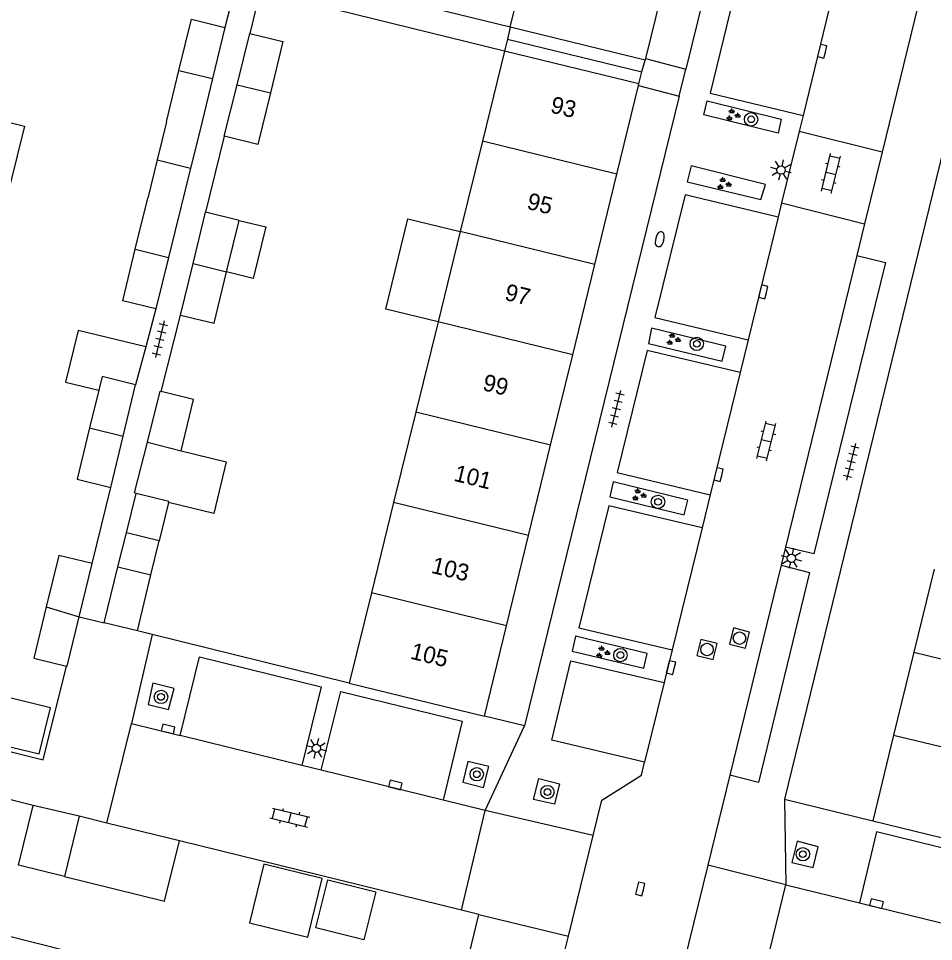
# Model space of a CAD drawing. Extents: x 128000 to 131008, y 398996 to 402500.
# Drawn here: x 128054.3 to 128108.9, y 399386.2 to 399441.3 of the extents above; entities that cross this region are included whole.
import ezdxf

# ---------------------------------------------------------------- set-up
doc = ezdxf.new("R2010")
doc.units = 0
for name, color, linetype in [('gg-afsc-erfafscheiding', 7, 'Continuous'), ('gg-afsc-muur', 7, 'Continuous'), ('gg-anno-huisnummerreeks BGT', 7, 'Continuous'), ('gg-bbg-bijgebouw', 7, 'Continuous'), ('gg-bbg-gedigitaliseerde bijgebouw', 7, 'Continuous'), ('gg-bbg-hoofdgebouw', 7, 'Continuous'), ('gg-bbg-luifel en loopbrug', 7, 'Continuous'), ('gg-bbg-onder overbouw', 7, 'Continuous'), ('gg-bbg-pand overbouw', 7, 'Continuous'), ('gg-bbg-tussenscheiding', 7, 'Continuous'), ('gg-bbg-tussenscheiding niveau 01', 7, 'Continuous'), ('gg-knt-verharding', 7, 'Continuous'), ('gg-knt-verharding nz', 7, 'Continuous'), ('gt-grn-weggrens', 7, 'Continuous'), ('gt-symb-boom', 7, 'Continuous'), ('gt-symb-brandkraan', 7, 'Continuous'), ('gt-symb-groenvak', 7, 'Continuous'), ('gt-symb-klinker verharding', 7, 'Continuous'), ('gt-symb-kolk', 7, 'Continuous'), ('gt-symb-lichtmast', 7, 'Continuous'), ('gt-symb-rioolschacht', 7, 'Continuous'), ('gt-symb-tegel verharding', 7, 'Continuous')]:
    doc.layers.add(name, color=color, linetype=linetype)

# ---------------------------------------------------------------- blocks, each defined once
blk = doc.blocks.new('gt0-KL1')
at = {"layer": 'gt-symb-klinker verharding'}
for p, q in [((-1.15, 0.3), (1.15, 0.3)), ((-1, -0.3), (-1, 0.3)), ((-0.5, 0.3), (-0.5, 0.45)), ((0, -0.3), (0, 0.3)), ((0.5, 0.3), (0.5, 0.45)), ((1, -0.3), (1, 0.3)), ((-1.15, -0.3), (1.15, -0.3)), ((-0.5, -0.45), (-0.5, -0.3)), ((0.5, -0.45), (0.5, -0.3))]:
    blk.add_line(p, q, dxfattribs=at)
blk = doc.blocks.new('gt0-KOLK')
at = {"layer": 'gt-symb-kolk'}
blk.add_lwpolyline([(0, 0), (0.375, 0), (0.375, 0.4), (-0.375, 0.4), (-0.375, 0), (0, 0)], dxfattribs=at)
blk = doc.blocks.new('gt0-TEG1')
at = {"layer": 'gt-symb-tegel verharding'}
for p, q in [((-1.125, 0), (1.125, 0)), ((-0.9, -0.25), (-0.9, 0.25)), ((-0.45, -0.25), (-0.45, 0.25)), ((0, -0.25), (0, 0.25)), ((0.45, -0.25), (0.45, 0.25)), ((0.9, -0.25), (0.9, 0.25))]:
    blk.add_line(p, q, dxfattribs=at)
blk = doc.blocks.new('gt0-LMAST')
at = {"layer": 'gt-symb-lichtmast'}
for p, q in [((-0.005, 0.246), (-0.005, 0.621)), ((-0.182, 0.173), (-0.447, 0.438)), ((0.172, 0.173), (0.437, 0.438)), ((-0.255, -0.004), (-0.63, -0.004)), ((-0.182, -0.181), (-0.447, -0.446)), ((-0.005, -0.254), (-0.005, -0.629)), ((0.437, -0.446), (0.172, -0.181)), ((0.245, -0.004), (0.62, -0.004))]:
    blk.add_line(p, q, dxfattribs=at)
blk.add_circle((-0.005, -0.004), 0.25, dxfattribs=at)
blk = doc.blocks.new('gt0-BOOM')
at = {"layer": 'gt-symb-boom'}
for radius in [0.4, 0.2]:
    blk.add_circle((0, 0), radius, dxfattribs=at)
blk = doc.blocks.new('gt0-GRVAK')
at = {"layer": 'gt-symb-groenvak'}
for p, q in [((-0.11, 0.189), (-0.228, 0.24)), ((-0.182, 0.153), (0.088, 0.153)), ((-0.091, 0.211), (-0.156, 0.322)), ((-0.047, 0.214), (-0.047, 0.393)), ((-0.004, 0.211), (0.061, 0.322)), ((0.015, 0.189), (0.133, 0.24)), ((0.262, -0.052), (0.197, 0.059)), ((0.305, -0.049), (0.305, 0.13)), ((0.349, -0.052), (0.414, 0.059)), ((-0.245, -0.228), (-0.363, -0.177)), ((-0.318, -0.264), (-0.047, -0.264)), ((-0.226, -0.206), (-0.291, -0.095)), ((-0.183, -0.203), (-0.183, -0.024)), ((-0.139, -0.206), (-0.074, -0.095)), ((-0.12, -0.228), (-0.002, -0.177)), ((0.243, -0.074), (0.125, -0.023)), ((0.17, -0.11), (0.441, -0.11)), ((0.368, -0.074), (0.486, -0.023))]:
    blk.add_line(p, q, dxfattribs=at)
blk = doc.blocks.new('gt0-BR')
at = {"layer": 'gt-symb-brandkraan'}
for centre, radius, start, end in [((-0.244, 0), 0.206, 107.5669, 252.4331), ((0.599, -2.664), 3, 106.892, 107.5669), ((0, -0.691), 0.938, 73.108, 106.892), ((-0.599, -2.664), 3, 72.4331, 73.108), ((0.244, 0), 0.206, 287.567, 72.4331), ((0.599, 2.664), 3, 252.4331, 253.108), ((0, 0.691), 0.938, 253.108, 286.8921), ((-0.599, 2.664), 3, 286.8921, 287.567)]:
    blk.add_arc(centre, radius, start, end, dxfattribs=at)
blk = doc.blocks.new('gt0-RS')
at = {"layer": 'gt-symb-rioolschacht'}
blk.add_lwpolyline([(-0.5, -0.5), (0.5, -0.5), (0.5, 0.5), (-0.5, 0.5)], close=True, dxfattribs=at)
blk.add_circle((0, 0), 0.375, dxfattribs=at)

msp = doc.modelspace()

# ---------------------------------------------------------------- linework, layer by layer
at = {"layer": 'gg-afsc-erfafscheiding'}
for p, q in [((128066.545, 399434.301), (128065.424, 399429.762)), ((128062.457, 399424.003), (128061.854, 399421.732)), ((128062.782, 399419.061), (128063.926, 399423.625)), ((128058.654, 399408.783), (128059.76, 399413.33)), ((128062.246, 399404.553), (128061.359, 399404.772)), ((128074.01, 399401.65), (128062.246, 399404.553))]:
    msp.add_line(p, q, dxfattribs=at)
for points in [[(128083.621, 399440.81), (128068.828, 399444.446), (128069.473, 399446.807)], [(128054.25, 399446.39), (128067.198, 399443.207), (128066.58, 399440.802)], [(128083.28, 399439.39), (128068.686, 399442.977), (128068.061, 399440.444)], [(128042.915, 399400.269), (128055.727, 399397.069), (128057.124, 399402.662)]]:
    msp.add_lwpolyline(points, dxfattribs=at)
at = {"layer": 'gg-afsc-muur'}
for p, q in [((128091.696, 399438.947), (128094.109, 399438.309)), ((128091.274, 399437.333), (128093.711, 399436.689)), ((128055.13, 399394.34), (128046.479, 399396.519)), ((128080.7, 399388.079), (128063.875, 399392.229)), ((128078.759, 399375.495), (128081.75, 399387.82)), ((128081.75, 399387.82), (128080.7, 399388.079))]:
    msp.add_line(p, q, dxfattribs=at)
at = {"layer": 'gg-bbg-bijgebouw'}
for p, q in [((128057.881, 399405.602), (128058.654, 399408.783)), ((128061.359, 399404.772), (128059.364, 399405.244)), ((128057.874, 399393.691), (128056.991, 399390.099)), ((128059.527, 399393.288), (128057.874, 399393.691)), ((128063.875, 399392.229), (128059.527, 399393.288))]:
    msp.add_line(p, q, dxfattribs=at)
for points in [[(128058.654, 399408.783), (128056.653, 399409.269), (128055.908, 399406.204)], [(128055.908, 399406.204), (128055.163, 399403.138), (128057.124, 399402.662)], [(128057.124, 399402.662), (128057.164, 399402.652), (128057.881, 399405.602)], [(128056.991, 399390.099), (128062.982, 399388.623), (128063.875, 399392.229)]]:
    msp.add_lwpolyline(points, dxfattribs=at)
at = {"layer": 'gg-bbg-gedigitaliseerde bijgebouw'}
for p, q in [((128066.58, 399440.802), (128065.837, 399437.742)), ((128067.303, 399437.373), (128068.061, 399440.444)), ((128063.091, 399435.167), (128063.835, 399438.228)), ((128065.837, 399437.742), (128065.093, 399434.681)), ((128066.545, 399434.301), (128067.303, 399437.373)), ((128063.091, 399435.167), (128062.53, 399432.891)), ((128065.093, 399434.681), (128064.531, 399432.405)), ((128062.53, 399432.891), (128061.968, 399430.615)), ((128064.531, 399432.405), (128063.969, 399430.128)), ((128061.223, 399427.55), (128061.968, 399430.615)), ((128063.969, 399430.128), (128063.213, 399427.066)), ((128064.675, 399426.694), (128065.424, 399429.762)), ((128067.427, 399429.273), (128065.424, 399429.762)), ((128063.213, 399427.066), (128062.457, 399424.003)), ((128063.926, 399423.625), (128064.675, 399426.694)), ((128059.05, 399419.132), (128058.503, 399416.882)), ((128060.505, 399416.395), (128061.25, 399419.46)), ((128059.76, 399413.33), (128060.505, 399416.395)), ((128059.364, 399405.244), (128060.194, 399408.593)), ((128060.194, 399408.593), (128062.165, 399408.112)), ((128061.359, 399404.772), (128062.165, 399408.112))]:
    msp.add_line(p, q, dxfattribs=at)
for points in [[(128063.835, 399438.228), (128064.579, 399441.288), (128066.58, 399440.802)], [(128068.061, 399440.444), (128070.048, 399439.959), (128069.298, 399436.886)], [(128069.298, 399436.886), (128068.548, 399433.812), (128066.545, 399434.301)], [(128067.427, 399429.273), (128069.017, 399428.885), (128068.269, 399425.817), (128066.679, 399426.205)], [(128062.457, 399424.003), (128060.478, 399424.484), (128061.223, 399427.55)], [(128063.926, 399423.625), (128065.93, 399423.136), (128066.679, 399426.205)], [(128061.25, 399419.46), (128059.248, 399419.947), (128059.05, 399419.132)], [(128061.949, 399416.04), (128062.707, 399419.079), (128062.782, 399419.061)], [(128063.959, 399415.512), (128064.71, 399418.59), (128062.782, 399419.061)], [(128058.503, 399416.882), (128057.758, 399413.816), (128059.76, 399413.33)], [(128061.281, 399412.977), (128061.19, 399413), (128061.949, 399416.04)], [(128063.959, 399415.512), (128066.654, 399414.862), (128065.91, 399411.782), (128063.208, 399412.434)], [(128063.208, 399412.434), (128063.222, 399412.49), (128061.281, 399412.977)], [(128052.734, 399398.086), (128055.491, 399397.418), (128056.159, 399400.174), (128053.402, 399400.843), (128052.734, 399398.086)]]:
    msp.add_lwpolyline(points, dxfattribs=at)
at = {"layer": 'gg-bbg-hoofdgebouw'}
for p, q in [((128083.621, 399440.81), (128084.958, 399446.269)), ((128092.989, 399444.224), (128091.696, 399438.947)), ((128083.28, 399439.39), (128081.957, 399434.005)), ((128091.696, 399438.947), (128091.67, 399438.84)), ((128089.983, 399432.045), (128091.274, 399437.333)), ((128091.274, 399437.333), (128091.3, 399437.44)), ((128081.957, 399434.005), (128080.633, 399428.612)), ((128088.666, 399426.65), (128089.983, 399432.045)), ((128080.633, 399428.612), (128079.308, 399423.218)), ((128087.349, 399421.255), (128088.666, 399426.65)), ((128079.308, 399423.218), (128077.983, 399417.825)), ((128086.032, 399415.86), (128087.349, 399421.255)), ((128077.983, 399417.825), (128076.658, 399412.432)), ((128084.715, 399410.465), (128086.032, 399415.86)), ((128076.658, 399412.432), (128075.334, 399407.039)), ((128083.398, 399405.07), (128084.715, 399410.465)), ((128108.939, 399408.448), (128107.729, 399403.497)), ((128075.334, 399407.039), (128074.01, 399401.65)), ((128082.08, 399399.67), (128083.398, 399405.07)), ((128107.729, 399403.497), (128106.517, 399398.536)), ((128074.01, 399401.65), (128082.08, 399399.67)), ((128106.517, 399398.536), (128105.27, 399393.43)), ((128105.27, 399393.43), (128113.99, 399391.29))]:
    msp.add_line(p, q, dxfattribs=at)
at = {"layer": 'gg-bbg-luifel en loopbrug'}
for p, q in [((128061.854, 399421.732), (128061.25, 399419.46)), ((128060.695, 399410.614), (128061.281, 399412.977)), ((128063.208, 399412.434), (128062.653, 399410.135)), ((128060.194, 399408.593), (128060.695, 399410.614)), ((128062.653, 399410.135), (128060.695, 399410.614)), ((128062.165, 399408.112), (128062.653, 399410.135)), ((128057.874, 399393.691), (128055.13, 399394.34))]:
    msp.add_line(p, q, dxfattribs=at)
for points in [[(128051.607, 399435.639), (128054.605, 399434.902), (128053.282, 399429.52), (128050.284, 399430.257)], [(128079.308, 399423.218), (128076.186, 399423.985), (128077.511, 399429.379), (128080.633, 399428.612)], [(128061.854, 399421.732), (128057.818, 399422.709), (128057.067, 399419.612), (128059.05, 399419.132)], [(128056.991, 399390.099), (128054.253, 399390.772), (128055.13, 399394.34)], [(128068.899, 399390.83), (128068.04, 399387.337), (128071.534, 399386.479), (128072.392, 399389.972), (128068.899, 399390.83)], [(128075.587, 399389.187), (128074.882, 399386.321), (128072.016, 399387.025), (128072.721, 399389.891), (128075.587, 399389.187)], [(128053.157, 399386.67), (128057.331, 399385.622), (128057.008, 399384.337), (128061.889, 399384.259), (128061.629, 399383.273)]]:
    msp.add_lwpolyline(points, dxfattribs=at)
at = {"layer": 'gg-bbg-onder overbouw'}
for p, q in [((128091.67, 399438.84), (128083.621, 399440.81)), ((128091.3, 399437.44), (128083.28, 399439.39))]:
    msp.add_line(p, q, dxfattribs=at)
at = {"layer": 'gg-bbg-pand overbouw'}
for p, q in [((128083.621, 399440.81), (128083.451, 399440.1)), ((128083.451, 399440.1), (128083.28, 399439.39)), ((128091.485, 399438.14), (128091.67, 399438.84)), ((128091.3, 399437.44), (128091.485, 399438.14))]:
    msp.add_line(p, q, dxfattribs=at)
at = {"layer": 'gg-bbg-tussenscheiding'}
for p, q in [((128063.835, 399438.228), (128065.837, 399437.742)), ((128067.303, 399437.373), (128069.298, 399436.886)), ((128089.983, 399432.045), (128081.957, 399434.005)), ((128062.53, 399432.891), (128064.531, 399432.405)), ((128066.679, 399426.205), (128067.427, 399429.273)), ((128088.666, 399426.65), (128080.633, 399428.612)), ((128061.223, 399427.55), (128063.213, 399427.066)), ((128064.675, 399426.694), (128066.679, 399426.205)), ((128087.349, 399421.255), (128079.308, 399423.218)), ((128086.032, 399415.86), (128077.983, 399417.825)), ((128058.503, 399416.882), (128060.505, 399416.395)), ((128061.949, 399416.04), (128063.959, 399415.512)), ((128084.715, 399410.465), (128076.658, 399412.432)), ((128083.398, 399405.07), (128075.334, 399407.039)), ((128055.908, 399406.204), (128057.881, 399405.602)), ((128107.729, 399403.497), (128116.454, 399401.358)), ((128106.517, 399398.536), (128115.245, 399396.419))]:
    msp.add_line(p, q, dxfattribs=at)
at = {"layer": 'gg-bbg-tussenscheiding niveau 01'}
msp.add_line((128083.451, 399440.1), (128091.485, 399438.14), dxfattribs=at)
at = {"layer": 'gg-knt-verharding'}
for p, q in [((128104.68, 399481.32), (128094.109, 399438.309)), ((128120.22, 399477.49), (128100.001, 399394.72)), ((128093.711, 399436.689), (128084.47, 399399.09)), ((128101.104, 399435.537), (128100.873, 399434.596)), ((128100.873, 399434.596), (128099.828, 399430.33)), ((128105.823, 399433.351), (128100.873, 399434.596)), ((128105.823, 399433.351), (128104.779, 399429.082)), ((128099.828, 399430.33), (128099.619, 399429.478)), ((128099.828, 399430.33), (128104.779, 399429.082)), ((128104.779, 399429.082), (128104.315, 399427.184)), ((128097.822, 399422.145), (128097.346, 399420.201)), ((128095.553, 399412.884), (128095.073, 399410.926)), ((128100.055, 399409.756), (128099.795, 399408.689)), ((128093.287, 399403.638), (128092.808, 399401.68)), ((128059.527, 399393.288), (128061, 399399.24)), ((128061, 399399.24), (128063.915, 399398.522)), ((128084.47, 399399.09), (128082.08, 399399.67)), ((128072.337, 399396.449), (128071.176, 399396.735)), ((128096.728, 399396.145), (128095.416, 399390.779)), ((128082.12, 399394.04), (128079.613, 399394.657)), ((128100.001, 399394.72), (128105.27, 399393.43)), ((128080.7, 399388.079), (128082.12, 399394.04)), ((128087.098, 399386.536), (128088.578, 399392.541)), ((128095.416, 399390.779), (128093.989, 399384.942)), ((128098.643, 399383.719), (128100.07, 399389.6)), ((128100.07, 399389.6), (128104.481, 399388.519)), ((128085.928, 399381.789), (128087.098, 399386.536))]:
    msp.add_line(p, q, dxfattribs=at)
for points in [[(128112.527, 399477.576), (128112.38, 399476.96), (128115.21, 399471.75), (128105.823, 399433.351)], [(128102.893, 399442.84), (128097.338, 399444.151), (128095.552, 399436.87), (128101.104, 399435.537)], [(128099.808, 399435.32), (128099.613, 399434.479), (128095.175, 399435.58), (128095.378, 399436.408), (128099.808, 399435.32)], [(128094.421, 399432.528), (128094.195, 399431.581), (128098.584, 399430.534), (128098.859, 399431.413), (128094.421, 399432.528)], [(128099.619, 399429.478), (128094.061, 399430.809), (128092.265, 399423.485), (128097.822, 399422.145)], [(128104.315, 399427.184), (128106.028, 399426.77), (128101.759, 399409.356), (128100.055, 399409.756)], [(128096.27, 399420.878), (128096.494, 399421.762), (128092.055, 399422.84), (128091.885, 399421.932), (128096.27, 399420.878)], [(128097.346, 399420.201), (128091.793, 399421.499), (128090.002, 399414.214), (128095.553, 399412.884)], [(128089.774, 399413.664), (128089.572, 399412.77), (128094.01, 399411.692), (128094.219, 399412.564), (128089.774, 399413.664)], [(128095.073, 399410.926), (128089.514, 399412.236), (128087.721, 399404.95), (128093.287, 399403.638)], [(128099.795, 399408.689), (128101.499, 399408.244), (128098.447, 399395.716), (128096.728, 399396.145)], [(128091.596, 399402.533), (128091.802, 399403.417), (128087.512, 399404.459), (128087.315, 399403.557), (128091.596, 399402.533)], [(128063.915, 399398.522), (128065.062, 399403.225), (128072.323, 399401.432), (128071.176, 399396.735)], [(128091.643, 399396.927), (128086.097, 399398.234), (128087.245, 399402.986), (128092.808, 399401.68)], [(128061.989, 399400.366), (128063.219, 399400.063), (128063.542, 399401.323), (128062.284, 399401.638), (128061.989, 399400.366)], [(128072.337, 399396.449), (128073.505, 399401.148), (128080.75, 399399.366), (128079.613, 399394.657)], [(128080.78, 399395.732), (128082.02, 399395.415), (128082.343, 399396.658), (128081.094, 399396.965), (128080.78, 399395.732)], [(128088.578, 399392.541), (128089.1, 399394.66), (128091.45, 399396.14), (128091.643, 399396.927)], [(128085.328, 399395.951), (128086.563, 399395.627), (128086.26, 399394.408), (128085.015, 399394.702), (128085.328, 399395.951)], [(128111.862, 399386.711), (128112.862, 399390.952), (128105.501, 399392.767), (128104.481, 399388.519)], [(128101.709, 399390.638), (128102.004, 399391.875), (128100.747, 399392.202), (128100.445, 399390.937), (128101.709, 399390.638)]]:
    msp.add_lwpolyline(points, dxfattribs=at)
at = {"layer": 'gg-knt-verharding nz'}
for p, q in [((128102.893, 399442.84), (128101.104, 399435.537)), ((128099.619, 399429.478), (128097.822, 399422.145)), ((128104.315, 399427.184), (128100.055, 399409.756)), ((128097.346, 399420.201), (128095.553, 399412.884)), ((128095.073, 399410.926), (128093.287, 399403.638)), ((128099.795, 399408.689), (128096.728, 399396.145)), ((128092.808, 399401.68), (128091.643, 399396.927)), ((128071.176, 399396.735), (128063.915, 399398.522)), ((128079.613, 399394.657), (128072.337, 399396.449)), ((128104.481, 399388.519), (128111.862, 399386.711))]:
    msp.add_line(p, q, dxfattribs=at)
at = {"layer": 'gt-grn-weggrens'}
for p, q in [((128093.711, 399436.689), (128094.109, 399438.309)), ((128057.881, 399405.602), (128059.364, 399405.244)), ((128062.246, 399404.553), (128061, 399399.24)), ((128082.12, 399394.04), (128084.47, 399399.09)), ((128100.001, 399394.72), (128100.07, 399389.6)), ((128088.578, 399392.541), (128082.12, 399394.04)), ((128100.07, 399389.6), (128095.416, 399390.779)), ((128081.75, 399387.82), (128087.098, 399386.536))]:
    msp.add_line(p, q, dxfattribs=at)

# ---------------------------------------------------------------- block references
at = {"layer": 'gt-symb-boom'}
for p in [(128098.007, 399435.314), (128094.763, 399421.904), (128092.446, 399412.47), (128090.199, 399403.32), (128062.764, 399400.819), (128081.621, 399396.201), (128085.842, 399395.141), (128101.095, 399391.43)]:
    msp.add_blockref('gt0-BOOM', p, dxfattribs=at)
at = {"layer": 'gt-symb-brandkraan', "rotation": 76.17220496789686}
msp.add_blockref('gt0-BR', (128092.549, 399428.154), dxfattribs=at)
at = {"layer": 'gt-symb-groenvak'}
for p in [(128096.905, 399435.565), (128096.365, 399431.46), (128093.34, 399422.17), (128091.288, 399412.88), (128089.128, 399403.481)]:
    msp.add_blockref('gt0-GRVAK', p, dxfattribs=at)
at = {"layer": 'gt-symb-klinker verharding'}
for p, rotation in [((128102.771, 399432.076), 76.17220496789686), ((128098.915, 399416.104), 76.17220496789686), ((128070.461, 399393.611), -13.647238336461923)]:
    msp.add_blockref('gt0-KL1', p, dxfattribs=dict(at, rotation=rotation))
at = {"layer": 'gt-symb-kolk'}
for p, rotation in [((128102.439, 399439.332), 76.22785456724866), ((128098.923, 399424.965), 76.22785456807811), ((128096.251, 399414.05), 76.22785456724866), ((128093.415, 399402.523), 76.22785456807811), ((128063.138, 399398.712), -13.827795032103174), ((128076.711, 399395.366), -13.827795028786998), ((128091.575, 399389.307), 76.22785456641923), ((128105.442, 399388.284), -13.772145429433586)]:
    msp.add_blockref('gt0-KOLK', p, dxfattribs=dict(at, rotation=rotation))
at = {"layer": 'gt-symb-lichtmast'}
for p, rotation in [((128099.791, 399432.286), 76.22785456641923), ((128100.409, 399409.104), 76.22785456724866), ((128072.045, 399397.756), -13.827795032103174)]:
    msp.add_blockref('gt0-LMAST', p, dxfattribs=dict(at, rotation=rotation))
at = {"layer": 'gt-symb-rioolschacht'}
for p, rotation in [((128097.311, 399404.332), 76.17220496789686), ((128095.373, 399403.653), 76.17220496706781)]:
    msp.add_blockref('gt0-RS', p, dxfattribs=dict(at, rotation=rotation))
at = {"layer": 'gt-symb-tegel verharding'}
for p, rotation in [((128062.694, 399422.187), -103.59156043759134), ((128089.959, 399418.02), 76.17220496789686), ((128103.981, 399414.866), 76.17220496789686)]:
    msp.add_blockref('gt0-TEG1', p, dxfattribs=dict(at, rotation=rotation))

# ---------------------------------------------------------------- texts
at = {"layer": 'gg-anno-huisnummerreeks BGT'}
for s, p in [('93', (128085.966, 399435.736)), ('95', (128084.56, 399429.977)), ('97', (128083.234, 399424.543)), ('99', (128081.918, 399419.152)), ('101', (128080.196, 399413.736)), ('103', (128078.854, 399408.238)), ('105', (128077.603, 399403.113))]:
    msp.add_text(s, height=1, rotation=346.3, dxfattribs=at).set_placement(p)

doc.saveas('drawing.dxf')
